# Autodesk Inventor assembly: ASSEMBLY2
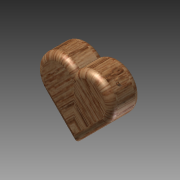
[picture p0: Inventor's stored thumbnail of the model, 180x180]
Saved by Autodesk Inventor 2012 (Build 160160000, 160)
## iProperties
Created: 2011-01
Part Number: ASSEMBLY2
Document SubType Name: Assembly
Designer: Microsoft
Author: Microsoft
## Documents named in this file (6)
- C:\Users\David\Desktop\Playground\3D work\Locket\ASSEMBLY2.iam
- C:\Users\David\Desktop\Playground\3D work\Locket\BASE2-TOP.ipt
- C:\Users\David\Desktop\Playground\3D work\Locket\BASE2.ipt
- C:\Users\David\Desktop\Playground\3D work\Locket\TOP2.ipt
- C:\Users\David\Desktop\Playground\3D work\Locket\BASE1.ipt
- C:\Users\David\Desktop\Playground\3D work\Locket\TOP1.ipt
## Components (5 placed, 5 different names)
1. BASE2-TOP:1 — Mate:10, Mate:11, Mate:12, Mate:13
2. BASE2:1 — Mate:7, Mate:8, Mate:9, Mate:12
3. TOP2:1 — Mate:3, Mate:7, Angle:1, Mate:13
4. BASE1:1 — Mate:1, Mate:2, Mate:8, Mate:9, Mate:10, Mate:11, Angle:2
5. TOP1:1 — Mate:1, Mate:2, Mate:3, Angle:1, Angle:2
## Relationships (12: Mate 10, Angle 2)
- Mate:1: BASE1:1 ↔ TOP1:1
- Mate:2: BASE1:1 ↔ TOP1:1
- Mate:3: TOP2:1 ↔ TOP1:1
- Mate:7: BASE2:1 ↔ TOP2:1
- Mate:8: BASE2:1 ↔ BASE1:1
- Mate:9: BASE2:1 ↔ BASE1:1
- Angle:1: TOP2:1 ↔ TOP1:1
- Mate:10: BASE2-TOP:1 ↔ BASE1:1
- Mate:11: BASE2-TOP:1 ↔ BASE1:1
- Mate:12: BASE2-TOP:1 ↔ BASE2:1
- Mate:13: BASE2-TOP:1 ↔ TOP2:1
- Angle:2: BASE1:1 ↔ TOP1:1
